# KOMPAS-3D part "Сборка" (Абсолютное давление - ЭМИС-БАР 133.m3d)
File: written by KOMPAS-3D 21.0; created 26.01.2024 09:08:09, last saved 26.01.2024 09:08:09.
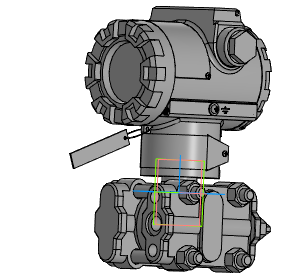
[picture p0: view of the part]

Document properties: Автор: Admin; Организация: office.local; Полное имя файла: S:\Эмис\Инженерный\Расходомеры и фильтры\Задачи\Черненков А.А\ЭМИС-БАР\3D-модели для сайта\Датчики абсолютного давления ЭМИС-БАР\Компоненты\Сборка.m3d

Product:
- Part/product: Сборка
    Масса: 7.133172

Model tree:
1. Операция без истории:1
